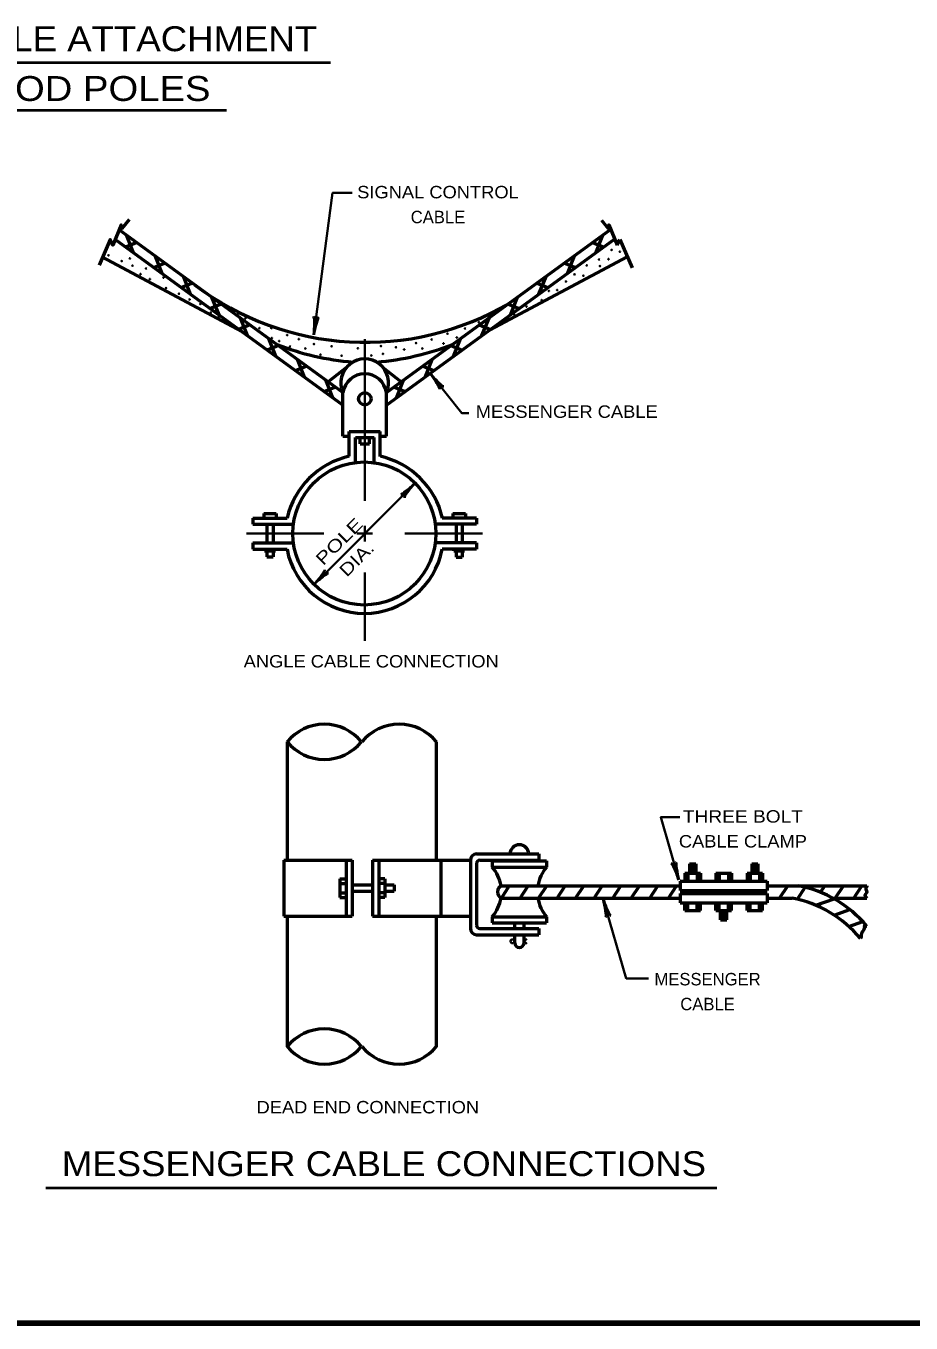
# Model space of a CAD drawing. Extents: x -421 to 434, y -46 to 498.
# Drawn here: x -96.1 to 74.7, y -34.2 to 216.1 of the extents above; entities that cross this region are included whole.
import ezdxf
from ezdxf.enums import TextEntityAlignment as Align

# ---------------------------------------------------------------- set-up
doc = ezdxf.new("R2010")
doc.units = 0
doc.header["$LTSCALE"] = 0.96
doc.layers.add('1', color=7, linetype='Continuous', lineweight=53)

msp = doc.modelspace()

# ---------------------------------------------------------------- linework, layer by layer
at = {"layer": '1', "lineweight": 40}
for p, q in [((-174.0904, 209.0297), (-37.3404, 209.0297)), ((-152.8823, 199.8058), (-57.4422, 199.8058)), ((-92.2826, -8.1201), (37.2529, -8.1201))]:
    msp.add_line(p, q, dxfattribs=at)
at = {"layer": '1'}
for p, q in [((-34.9323, 145.3319), (-78.1363, 176.7213)), ((-75.3448, 172.2933), (-76.7173, 175.6904)), ((-26.5345, 145.3319), (16.7414, 176.7733)), ((13.8782, 172.2933), (15.2507, 175.6904)), ((-34.9322, 142.9318), (-78.9055, 174.8802)), ((-74.7571, 174.2662), (-76.8799, 173.4086)), ((-26.5344, 142.9318), (17.5105, 174.9322)), ((13.2905, 174.2662), (15.4133, 173.4086)), ((17.9938, 173.7754), (18.5366, 174.8615)), ((18.5366, 174.8615), (20.8632, 169.3866)), ((-54.4651, 157.1233), (-81.3688, 171.4282)), ((-69.292, 170.2956), (-71.4147, 169.4379)), ((-69.849, 168.3003), (-71.2215, 171.6974)), ((-6.6325, 157.3914), (19.9535, 171.5273)), ((7.8254, 170.2956), (9.9481, 169.4379)), ((8.3824, 168.3003), (9.7549, 171.6974)), ((-64.3532, 164.3074), (-65.7256, 167.7045)), ((2.8866, 164.3074), (4.259, 167.7045)), ((-63.9746, 166.4323), (-66.0974, 165.5746)), ((2.508, 166.4323), (4.6308, 165.5746)), ((-58.8572, 160.3143), (-60.2296, 163.7114)), ((-2.6094, 160.3143), (-1.237, 163.7114)), ((-58.4448, 162.4147), (-60.5676, 161.557)), ((-3.0218, 162.4147), (-0.899, 161.557)), ((-52.8877, 158.3772), (-55.0105, 157.5195)), ((-53.3614, 156.3214), (-54.7339, 159.7185)), ((-8.5789, 158.3772), (-6.4561, 157.5195)), ((-8.1052, 156.3214), (-6.7327, 159.7185)), ((-47.8655, 152.3284), (-49.238, 155.7256)), ((-13.6011, 152.3284), (-12.2286, 155.7256)), ((-47.3951, 154.3866), (-49.5179, 153.529)), ((-14.0715, 154.3866), (-11.9487, 153.529)), ((-41.9309, 150.4166), (-44.0537, 149.559)), ((-42.3695, 148.3353), (-43.742, 151.7325)), ((-34.2119, 150.2214), (-37.8017, 147.4167)), ((-27.2933, 150.2214), (-23.7035, 147.4167)), ((-19.5357, 150.4166), (-17.4129, 149.559)), ((-19.0971, 148.3353), (-17.7246, 151.7325)), ((-36.8738, 144.3424), (-38.2463, 147.7396)), ((-24.5928, 144.3424), (-23.2203, 147.7396)), ((-36.41, 146.4055), (-38.5328, 145.5478)), ((-34.9344, 136.9318), (-34.9344, 145.3318)), ((-26.5344, 136.9318), (-26.5344, 145.3318)), ((-25.0566, 146.4055), (-22.9338, 145.5478)), ((-33.7344, 137.8318), (-27.7344, 137.8318)), ((-33.7344, 133.0318), (-33.7344, 137.8318)), ((-27.7344, 133.0099), (-27.7344, 137.8318)), ((-34.9344, 136.9318), (-33.7344, 136.9318)), ((-32.5344, 131.8318), (-32.5344, 136.6318)), ((-32.5344, 136.6318), (-28.9344, 136.6318)), ((-31.6344, 135.4318), (-31.6344, 136.6318)), ((-31.6344, 135.4318), (-29.8344, 135.4318)), ((-29.8344, 135.4318), (-29.8344, 136.6318)), ((-28.9344, 131.8099), (-28.9344, 136.6318)), ((-27.7344, 136.9318), (-26.5344, 136.9318)), ((-52.3344, 121.1214), (-45.7344, 121.1214)), ((-52.3344, 121.1214), (-52.3344, 119.9214)), ((-50.2344, 122.0214), (-47.8344, 122.0214)), ((-50.2344, 122.0214), (-50.2344, 121.1214)), ((-47.8344, 122.0214), (-47.8344, 121.1214)), ((-9.1852, 121.1214), (-15.7852, 121.1214)), ((-13.6963, 122.0018), (-11.2963, 122.0018)), ((-13.6963, 122.0018), (-13.6963, 121.1018)), ((-11.2963, 122.0018), (-11.2963, 121.1018)), ((-9.1852, 121.1214), (-9.1852, 119.9214)), ((-52.3344, 119.9214), (-44.5022, 119.9214)), ((-49.6344, 119.9214), (-49.6344, 116.3214)), ((-48.4344, 119.9214), (-48.4344, 116.3214)), ((-9.1852, 119.9214), (-17.1334, 119.9214)), ((-13.0963, 119.9018), (-13.0963, 116.3018)), ((-11.8963, 119.9018), (-11.8963, 116.3018)), ((-52.3344, 116.3214), (-44.4976, 116.3214)), ((-52.3344, 116.3214), (-52.3344, 115.1214)), ((-9.1852, 116.3214), (-17.138, 116.3214)), ((-9.1852, 116.3214), (-9.1852, 115.1214)), ((-52.3344, 115.1214), (-45.7344, 115.1214)), ((-50.0844, 114.8214), (-50.0844, 115.1214)), ((-50.0844, 114.8214), (-47.9844, 114.8214)), ((-49.6344, 114.8214), (-49.6344, 113.6214)), ((-49.6344, 113.6214), (-48.4344, 113.6214)), ((-48.4344, 114.8214), (-48.4344, 113.6214)), ((-47.9844, 114.8214), (-47.9844, 115.1214)), ((-9.1852, 115.1214), (-15.7852, 115.1214)), ((-13.5463, 114.8018), (-13.5463, 115.1018)), ((-13.5463, 114.8018), (-11.4463, 114.8018)), ((-13.0963, 114.8018), (-13.0963, 113.6018)), ((-13.0963, 113.6018), (-11.8963, 113.6018)), ((-11.8963, 114.8018), (-11.8963, 113.6018)), ((-45.7344, 77.9214), (-45.7344, 55.1214)), ((-16.9344, 77.9214), (-16.9344, 55.1214)), ((-46.3344, 55.1214), (-46.3344, 44.3214)), ((-46.3344, 55.1214), (-33.1344, 55.1214)), ((-34.3344, 55.1214), (-34.3344, 44.3214)), ((-33.1344, 55.1214), (-33.1344, 44.3214)), ((-29.2344, 55.1214), (-10.3344, 55.1214)), ((-29.2344, 55.1214), (-29.2344, 44.3214)), ((-28.0344, 55.1214), (-28.0344, 44.3214)), ((-16.0344, 55.1214), (-16.0344, 44.3214)), ((-10.3344, 55.1214), (-10.3344, 41.9214)), ((-9.1344, 56.3214), (2.8656, 56.3214)), ((-8.5344, 55.1214), (2.8656, 55.1214)), ((2.8656, 56.3214), (2.8656, 55.1214)), ((-9.1344, 54.5214), (-9.1344, 42.5214)), ((-6.1344, 54.9876), (4.3656, 54.9876)), ((-6.1344, 54.9876), (-6.1344, 53.7876)), ((-6.1344, 53.7876), (4.3656, 53.7876)), ((4.3656, 54.9876), (4.3656, 53.7876)), ((31.0656, 52.5876), (31.0656, 51.0876)), ((31.0656, 52.5876), (34.0656, 52.5876)), ((31.6656, 52.5876), (31.6656, 51.0876)), ((31.9656, 54.3876), (31.9656, 52.5876)), ((31.9656, 54.3876), (33.1656, 54.3876)), ((31.9656, 53.7876), (33.1656, 53.7876)), ((31.9656, 53.1876), (33.1656, 53.1876)), ((32.2656, 54.0876), (32.8656, 54.0876)), ((32.2656, 53.4876), (32.8656, 53.4876)), ((32.2656, 52.8876), (32.8656, 52.8876)), ((33.1656, 54.3876), (33.1656, 52.5876)), ((33.4656, 52.5876), (33.4656, 51.0876)), ((34.0656, 52.5876), (34.0656, 51.0876)), ((37.0656, 52.5876), (37.0656, 51.0876)), ((37.0656, 52.5876), (40.0656, 52.5876)), ((37.6656, 52.5876), (37.6656, 51.0876)), ((39.4656, 52.5876), (39.4656, 51.0876)), ((40.0656, 52.5876), (40.0656, 51.0876)), ((43.0748, 52.5876), (43.0748, 51.0876)), ((43.0748, 52.5876), (46.0748, 52.5876)), ((43.6748, 52.5876), (43.6748, 51.0876)), ((43.9748, 54.3876), (43.9748, 52.5876)), ((43.9748, 54.3876), (45.1748, 54.3876)), ((43.9748, 53.7876), (45.1748, 53.7876)), ((43.9748, 53.1876), (45.1748, 53.1876)), ((44.2748, 54.0876), (44.8748, 54.0876)), ((44.2748, 53.4876), (44.8748, 53.4876)), ((44.2748, 52.8876), (44.8748, 52.8876)), ((45.1748, 54.3876), (45.1748, 52.5876)), ((45.4748, 52.5876), (45.4748, 51.0876)), ((46.0748, 52.5876), (46.0748, 51.0876)), ((-35.5344, 51.5214), (-35.5344, 47.9214)), ((-35.5344, 51.5214), (-34.3344, 51.5214)), ((-35.5344, 50.6214), (-34.3344, 50.6214)), ((-33.1344, 50.3214), (-29.2344, 50.3214)), ((-26.8466, 51.5214), (-28.0466, 51.5214)), ((-26.8466, 50.6214), (-28.0466, 50.6214)), ((-26.8466, 51.5214), (-26.8466, 47.9214)), ((-26.8466, 50.3214), (-25.0466, 50.3214)), ((-25.0466, 50.3214), (-25.0466, 49.1214)), ((-4.3344, 47.7876), (-2.7692, 50.1919)), ((-4.3344, 50.1876), (30.1656, 50.1876)), ((-0.7548, 47.7876), (0.8076, 50.1876)), ((2.8248, 47.7876), (4.3872, 50.1876)), ((6.4045, 47.7876), (7.9669, 50.1876)), ((9.9842, 47.7876), (11.5466, 50.1876)), ((13.5638, 47.7876), (15.1262, 50.1876)), ((17.1435, 47.7876), (18.7059, 50.1876)), ((20.7232, 47.7876), (22.2856, 50.1876)), ((24.3029, 47.7876), (25.8653, 50.1876)), ((27.8826, 47.7876), (29.445, 50.1876)), ((30.1656, 51.0876), (46.9656, 51.0876)), ((30.1656, 51.0876), (30.1656, 49.2876)), ((46.9656, 51.0876), (46.9656, 49.2876)), ((46.9656, 50.1876), (66.1656, 50.1876)), ((49.3606, 47.7876), (50.923, 50.1876)), ((57.258, 48.9212), (58.0824, 50.1876)), ((60.0996, 47.7876), (61.662, 50.1876)), ((63.6792, 47.7876), (65.2416, 50.1876)), ((-35.5344, 48.8214), (-34.3344, 48.8214)), ((-35.5344, 47.9214), (-34.3344, 47.9214)), ((-33.1344, 49.1214), (-29.2344, 49.1214)), ((-26.8466, 48.8214), (-28.0466, 48.8214)), ((-26.8466, 47.9214), (-28.0466, 47.9214)), ((-26.8466, 49.1214), (-25.0466, 49.1214)), ((-4.3344, 47.7876), (30.1656, 47.7876)), ((30.1656, 49.2876), (46.9656, 49.2876)), ((30.1656, 48.6876), (46.9656, 48.6876)), ((30.1656, 48.6876), (30.1656, 46.8876)), ((46.9656, 48.6876), (46.9656, 46.8876)), ((46.9656, 47.7876), (51.7656, 47.7876)), ((52.7966, 47.5667), (54.3089, 49.8898)), ((56.3419, 46.4036), (59.8608, 47.6639)), ((59.6388, 47.7876), (66.1656, 47.7876)), ((30.1656, 46.8876), (46.9656, 46.8876)), ((31.0656, 45.3992), (31.0656, 46.8992)), ((31.0656, 45.3992), (34.0656, 45.3992)), ((31.6656, 45.3992), (31.6656, 46.8992)), ((33.4656, 45.3992), (33.4656, 46.8992)), ((34.0656, 45.3992), (34.0656, 46.8992)), ((37.0656, 45.3992), (37.0656, 46.8992)), ((37.0656, 45.3992), (40.0656, 45.3992)), ((37.6656, 45.3992), (37.6656, 46.8992)), ((37.9656, 43.5992), (37.9656, 45.3992)), ((38.2656, 45.0992), (38.8656, 45.0992)), ((39.1656, 43.5992), (39.1656, 45.3992)), ((39.4656, 45.3992), (39.4656, 46.8992)), ((40.0656, 45.3992), (40.0656, 46.8992)), ((43.0748, 45.3992), (43.0748, 46.8992)), ((43.0748, 45.3992), (46.0748, 45.3992)), ((43.6748, 45.3992), (43.6748, 46.8992)), ((45.4748, 45.3992), (45.4748, 46.8992)), ((46.0748, 45.3992), (46.0748, 46.8992)), ((59.9193, 44.4983), (62.9344, 45.5781)), ((-46.3344, 44.3214), (-33.1344, 44.3214)), ((-45.7344, 44.3214), (-45.7344, 19.1214)), ((-29.2344, 44.3214), (-10.3344, 44.3214)), ((-16.9344, 44.3214), (-16.9344, 19.1214)), ((-6.1344, 44.1876), (4.3656, 44.1876)), ((-6.1344, 44.1876), (-6.1344, 42.9876)), ((-6.1344, 42.9876), (4.3656, 42.9876)), ((-1.7844, 41.9214), (-1.7844, 42.9876)), ((0.0156, 41.9214), (0.0156, 42.9876)), ((4.3656, 44.1876), (4.3656, 42.9876)), ((37.9656, 44.7992), (39.1656, 44.7992)), ((37.9656, 44.1992), (39.1656, 44.1992)), ((37.9656, 43.5992), (39.1656, 43.5992)), ((38.2656, 44.4992), (38.8656, 44.4992)), ((38.2656, 43.8992), (38.8656, 43.8992)), ((62.7367, 42.3208), (65.394, 43.2725)), ((-9.1344, 40.7214), (2.8656, 40.7214)), ((-8.5344, 41.9214), (2.8656, 41.9214)), ((-1.7844, 39.0876), (-1.7844, 40.7214)), ((0.0156, 39.0876), (0.0156, 40.7214)), ((2.8656, 41.9214), (2.8656, 40.7214))]:
    msp.add_line(p, q, dxfattribs=at)
at = {"layer": '1', "lineweight": 35}
for p, q in [((-30.7344, 124.4214), (-30.7344, 155.6214)), ((-40.5252, 108.3306), (-21.0094, 127.8464)), ((-53.5344, 118.1214), (-38.6178, 118.1214)), ((-32.2344, 118.1214), (-29.2344, 118.1214)), ((-30.7344, 116.6214), (-30.7344, 119.6214)), ((-23.0178, 118.1214), (-7.9852, 118.1214)), ((-30.7344, 110.6214), (-30.7344, 97.4214)), ((0.0725, 39.4658), (0.5498, 39.9432)), ((0.0725, 39.4658), (0.5498, 38.9885))]:
    msp.add_line(p, q, dxfattribs=at)
at = {"layer": '1', "lineweight": 158}
msp.add_line((427.565, -34.2024), (-364.035, -34.2024), dxfattribs=at)
at = {"layer": '1', "lineweight": 35}
for points in [[(-40.5673, 156.5091), (-36.9306, 183.8664), (-33.183, 183.8986)], [(-18.0201, 148.9585), (-11.971, 141.3514), (-10.6229, 141.386)], [(29.8777, 51.2958), (26.4182, 63.3757), (30.0995, 63.3757)], [(15.3213, 47.5739), (19.7601, 32.2945), (24.0135, 32.2945)]]:
    msp.add_lwpolyline(points, dxfattribs=at)
at = {"layer": '1'}
for points in [[(-76.2377, 178.7165), (-77.6028, 176.9947), (-77.7385, 177.6735), (-79.367, 173.7754), (-79.9098, 174.8615), (-82.0033, 169.9352)], [(14.9406, 178.6205), (16.2296, 176.9947), (16.3653, 177.6735), (17.9938, 173.7754)], [(66.1656, 50.1876), (66.1792, 49.9943), (66.0224, 49.6808), (65.9833, 49.4848), (66.1008, 49.2105), (66.1792, 48.9753), (66.14, 48.8185), (65.9441, 48.5442), (65.7874, 48.309), (65.9441, 48.1523), (66.0616, 47.9171), (66.1656, 47.7876)], [(66.1656, 42.3876), (65.6698, 42.3518), (65.8266, 42.1951), (65.7874, 42.0775), (65.5915, 41.8815), (65.5915, 41.6464), (65.5523, 41.6072), (65.3564, 41.3329), (65.278, 41.1369), (65.1605, 41.0193), (65.0821, 40.6666), (65.0821, 40.1963), (64.9656, 39.9876)]]:
    msp.add_lwpolyline(points, dxfattribs=at)
at = {"layer": '1', "lineweight": 35}
for centre in [(16.9218, 172.8538), (-80.2069, 171.8229), (-77.6465, 170.708), (-76.0801, 171.2203), (14.5014, 170.9947), (16.3167, 171.0812), (18.521, 172.508), (-75.568, 169.804), (-74.0317, 168.1769), (-72.9473, 169.2616), (9.747, 168.1412), (11.4759, 167.8818), (12.1242, 169.8706), (14.6743, 169.7409), (-72.2244, 167.2126), (-69.5736, 167.514), (-69.0916, 165.4951), (6.419, 165.1147), (8.1046, 166.7577), (-66.5914, 164.4103), (-64.5431, 163.2954), (3.4367, 163.1691), (4.8198, 164.9418), (-62.4646, 162.4216), (-60.4765, 160.7643), (-55.1749, 160.5232), (-6.742, 160.121), (-1.8363, 160.3156), (0.4977, 161.9153), (-59.0306, 159.8904), (-53.7591, 159.6795), (-51.0782, 157.751), (-48.7542, 157.751), (-11.3666, 157.6998), (-8.7085, 158.8888), (-48.6767, 155.8525), (-47.2436, 155.2713), (-45.6943, 156.4337), (-43.4478, 155.62), (-17.8066, 155.5813), (-14.7595, 156.6838), (-12.9442, 155.9488), (-45.152, 154.2252), (-42.2083, 153.8377), (-40.5428, 154.6901), (-39.2646, 152.6366), (-37.1343, 154.2639), (-32.0603, 153.8765), (-27.606, 154.3027), (-27.2187, 152.7916), (-24.7011, 154.0702), (-23.113, 153.644), (-20.8278, 154.8839), (-19.6271, 153.8377), (-15.5375, 154.803), (-35.1977, 152.4429), (-29.4652, 152.4816)]:
    msp.add_circle(centre, 0.0678, dxfattribs=at)
at = {"layer": '1'}
for centre, radius in [((-30.725, 144.1225), 1.2), ((-30.8178, 118.139), 13.8)]:
    msp.add_circle(centre, radius, dxfattribs=at)
for centre, radius, start, end in [((-30.5344, 209.6635), 54.6425, 232.79972, 300.56324), ((-28.61, 203.8437), 52.8143, 248.83745, 265.22991), ((-32.8894, 203.8437), 52.8143, 274.79911, 291.24419), ((-30.7344, 147.2094), 4.6006, 335.91356, 204.08644), ((-30.7344, 144.6818), 4.25, 8.79741, 171.20259), ((-30.2656, 117.5365), 15.8788, 102.61843, 166.95216), ((-31.1892, 117.5365), 15.8788, 13.04784, 77.38157), ((-30.7598, 117.9754), 15.2441, 190.79056, 349.20944), ((-38.5344, 72.0334), 9.301, 39.27573, 140.72427), ((-24.0676, 72.0334), 9.301, 39.27573, 140.72427), ((-38.5344, 83.837), 9.301, 219.27573, 320.72427), ((-0.8844, 56.2922), 1.8002, 0.92934, 179.07066), ((-9.1344, 55.1214), 1.2, 90, 180), ((-8.5344, 54.5214), 0.6, 90, 180), ((-11.6344, 48.9876), 7.3, 9.07313, 41.11209), ((9.8808, 48.9876), 7.3, 138.88791, 170.53858), ((-3.7516, 48.9876), 1.334, 115.90299, 244.09701), ((48.746, 27.9776), 22.6073, 39.59864, 79.2429), ((-11.6344, 48.9876), 7.3, 318.88791, 350.92687), ((9.8808, 48.9876), 7.3, 189.46143, 221.11209), ((47.546, 25.5776), 22.6073, 39.59864, 79.2429), ((-9.1344, 41.9214), 1.2, 180, 270), ((-8.5344, 42.5214), 0.6, 180, 270), ((-0.8844, 39.187), 0.9055, 186.30051, 353.69949), ((-38.5344, 13.2546), 9.301, 39.27573, 140.72427), ((-38.5344, 25.0582), 9.301, 219.27573, 320.72427), ((-24.0676, 25.0582), 9.301, 219.27573, 320.72427)]:
    msp.add_arc(centre, radius, start, end, dxfattribs=at)
at = {"layer": '1', "lineweight": 35}
for centre, radius, start, end in [((-2.2591, 39.4653), 0.3602, 75.19279, 284.80721), ((-2.3658, 39.2152), 0.6304, 28.89529, 71.61936), ((-2.3628, 39.7117), 0.626, 288.22327, 331.26209)]:
    msp.add_arc(centre, radius, start, end, dxfattribs=at)
at = {"layer": '1', "lineweight": 40}
for centre, major_axis, ratio, start_param, end_param in [((-40.7234, 157.8508), (-0.0966, -2.1488), 0.122415, 0.89635335, 3.14159265), ((-40.1384, 157.8085), (-0.4867, -2.0616), 0.07063, 3.14071475, 5.41810995), ((-17.382, 147.748), (-1.1469, 1.7809), 0.07063, 3.14071475, 5.41810995), ((-16.9456, 148.14), (-1.4804, 1.5606), 0.122415, 0.89635335, 3.14159265), ((-22.1397, 127.0752), (-1.6394, -1.3414), 0.07063, 6.28230741, 8.55970261), ((-22.1397, 127.0752), (-1.6394, -1.3414), 0.07063, 6.28230741, 8.55970261), ((-21.7009, 126.686), (1.3827, 1.6477), 0.122415, 0.89635335, 3.14159265), ((-21.7009, 126.686), (1.3827, 1.6477), 0.122415, 0.89635335, 3.14159265), ((-39.8337, 109.491), (-1.3827, -1.6477), 0.122415, 0.89635335, 3.14159265), ((-39.3949, 109.1018), (1.6394, 1.3414), 0.07063, 6.28230741, 8.55970261), ((29.1984, 52.4634), (0.7701, -2.0084), 0.122415, 0.89635335, 3.14159265), ((29.1984, 52.4634), (0.7701, -2.0084), 0.122415, 0.89635335, 3.14159265), ((29.7516, 52.6583), (-0.3777, 2.0843), 0.07063, 6.28230741, 8.55970261), ((29.7516, 52.6583), (-0.3777, 2.0843), 0.07063, 6.28230741, 8.55970261), ((15.4526, 46.2118), (0.3856, -2.0829), 0.07063, 6.28230741, 8.55970261), ((16.005, 46.4089), (-0.7777, 2.0055), 0.122415, 0.89635335, 3.14159265)]:
    msp.add_ellipse(centre, major_axis=major_axis, ratio=ratio, start_param=start_param, end_param=end_param, dxfattribs=at)

# ---------------------------------------------------------------- texts
at = {"layer": '1'}
for s, height, width, p in [('INTERCONNECT CABLE ATTACHMENT', 4.8, 1.1, (-105.6255, 211.1991)), ('METAL OR WOOD POLES', 4.8, 1.15, (-105.6254, 201.5991)), ('SIGNAL CONTROL', 2.4, 1.1, (-16.5966, 182.8073)), ('MESSENGER CABLE', 2.4, 1.1, (8.256, 140.4552)), ('ANGLE CABLE CONNECTION', 2.4, 1.1, (-29.4882, 92.2856)), ('THREE BOLT', 2.4, 1.15, (42.2675, 62.3531)), ('CABLE CLAMP', 2.4, 1.1, (42.2677, 57.5531)), ('DEAD END CONNECTION', 2.4, 1.1, (-30.1394, 6.252)), ('MESSENGER CABLE CONNECTIONS', 4.8, 1.1, (-27.0283, -5.8549))]:
    msp.add_text(s, height=height, dxfattribs=dict(at, width=width)).set_placement(p, align=Align.CENTER)
for s, p in [('CABLE', (-16.5965, 178.0073)), ('MESSENGER', (35.4464, 30.9504)), ('CABLE', (35.4464, 26.1504))]:
    msp.add_text(s, height=2.4, dxfattribs=at).set_placement(p, align=Align.CENTER)
for s, width, p in [('POLE', 1.3, (-34.831, 115.762)), ('DIA.', 1.25, (-31.4369, 112.3678))]:
    msp.add_text(s, height=2.4, rotation=45, dxfattribs=dict(at, width=width)).set_placement(p, align=Align.CENTER)

doc.saveas('drawing.dxf')
